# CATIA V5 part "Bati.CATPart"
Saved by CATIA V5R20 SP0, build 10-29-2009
Part number: Bati
Publications: "Hauteur_AxeA"
Bounding box of the stored display mesh (mm): x -50 to 80, y -275.237 to 100, z 0 to 503.17
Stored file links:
  F:\IAO\Projet_IAO5.0\Bati.CATPart
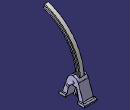
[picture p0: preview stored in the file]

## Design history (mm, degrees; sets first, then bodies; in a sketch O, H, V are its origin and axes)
Parameters
  Hauteur_AxeA = 120 mm
Body1 (main body)
  Sketch1 on yz-plane, origin (0, 0, 0), H (0, 1, 0), V (0, 0, 1)
    point P1 (0, 120)
    point P2 (42.4456, 134.9456)
    point P3 (100, 0)
    arc A1 centre (0, 120) radius 45 from (42.4456, 134.9456) to (0, 165) ccw
    axis line L1 (0, 0) -> (0, 145)
    point P5 (0, 165)
    arc A2 centre (90, 30) radius 10 from (80.5676, 26.6788) to (90, 20) ccw
    point P6 (90, 30)
    arc A3 centre (90, 10) radius 10 from (100, 10) to (90, 20) ccw
    line L2 (100, 0) -> (100, 10)
    point P8 (100, 10)
    line L3 (42.4456, 134.9456) -> (80.5676, 26.6788)
    point P9 (80.5676, 26.6788)
    point P10 (90, 20)
    point P11 (0, 0)
    point P12 (-100, 0)
    point P13 (-100, 10)
    line L4 (-100, 0) -> (-100, 10)
    point P14 (-90, 20)
    arc A4 centre (-90, 10) radius 10 from (-100, 10) to (-90, 20) cw
    point P16 (-80.5676, 26.6788)
    arc A5 centre (-90, 30) radius 10 from (-80.5676, 26.6788) to (-90, 20) cw
    point P18 (-42.4456, 134.9456)
    line L5 (-42.4456, 134.9456) -> (-80.5676, 26.6788)
    point P19 (0, 165)
    arc A6 centre (0, 120) radius 45 from (-42.4456, 134.9456) to (0, 165) cw
    line L6 (100, 0) -> (-100, 0)
    distance P1 O = 120 {= Hauteur_AxeA}
    radius A1 = 45
    distance P3 O = 100
    radius A2 = 10
    radius A3 = 10
    distance P6 L1 = 90
    coincidence: P3 H, L1 P5, P1 V, O P11, P5 P19
    vertical: L1 V, L2 V
    tangency: L2 A3, A2 A3, L3 A2, A1 L3, L6 A3
    symmetry: O P11 L1, P3 P12 L1, P8 P13 L1, L2 L4 L1, P10 P14 L1, A3 A4 L1, P9 P16 L1, A2 A5 L1, P2 P18 L1, L3 L5 L1, P5 P19 L1, A1 A6 L1
  Pad1: profile Sketch1, direction (1, 0, 0), length 40, mirrored extent
  Sketch2 on yz-plane, origin (0, 0, 0), H (0, 1, 0), V (0, 0, 1)
    arc A1 centre (90, 10) radius 10 from (100, 10) to (90, 20) ccw
    point P1 (90, 10)
    line L1 (0, 20) -> (90, 20)
    point P2 (0, 20)
    point P3 (90, 20)
    point P4 (100, 0)
    line L2 (100, 0) -> (100, 10)
    point P5 (100, 10)
    point P6 (100, 10)
    point P7 (-100, 0)
    point P8 (-100, 10)
    line L3 (-100, 0) -> (-100, 10)
    point P9 (-90, 20)
    point P10 (-100, 10)
    arc A2 centre (-90, 10) radius 10 from (-100, 10) to (-90, 20) cw
    point P12 (0, 20)
    line L4 (0, 20) -> (-90, 20)
    line L5 (100, 0) -> (-100, 0)
    radius A1 = 10
    distance V P1 = 90
    distance P2 H = 20
    coincidence: P2 V, L2 P6, L5 H, P5 A1, P2 P12, P5 P6, P8 P10
    tangency: L1 A1, A1 L2, L5 A1
    vertical: L2 V
    symmetry: P4 P7 V, P5 P8 V, L2 L3 V, P3 P9 V, P6 P10 V, A1 A2 V, P2 P12 V, L1 L4 V
  Pad2: profile Sketch2, direction (1, 0, 0), length 50, mirrored extent
  Sketch3 on end face of Pad2, origin (50, 0, 0), H (0, 1, 0), V (0, 0, 1)
    point P1 (-50, 0)
    line L1 (-50, 0) -> (-30, 100)
    line L2 (-30, 100) -> (30, 100)
    point P3 (30, 100)
    line L3 (30, 100) -> (50, 0)
    point P4 (50, 0)
    line L4 (50, 0) -> (-50, 0)
    axis line L5 (0, -25) -> (0, 128)
    point P5 (0, -25)
    distance L5 P3 = 30
    length L2 = 60
    distance H L2 = 100 {= Hauteur_AxeA -20mm}
    length L4 = 100
    distance L5 P4 = 50
    coincidence: P1 H, P4 H, P5 V
    horizontal: L2 H, L4 H
    vertical: L5 V
  Pocket1: profile Sketch3, direction (-1, 0, 0), length 80
  Sketch4 on face of Pocket1 from Sketch3.L2, origin (0, 0, 100), H (1, 0, 0), V (0, -1, 0)
    line L1 (-30, 30) -> (20, 30)
    line L2 (20, 30) -> (20, -30)
    line L3 (20, -30) -> (-30, -30)
    line L4 (-30, -30) -> (-30, 30)
    length L1 = 50
    distance L1 L3 = 60
    distance L1 H = 30
    distance L4 V = 30
    horizontal: L1 H, L3 H
    vertical: L2 V, L4 V
  Pocket2: profile Sketch4, direction (0, 0, -1), up to face of Pad1 from Sketch1.A1
  Sketch5 on end face of Pad1, origin (40, 0, 0), H (0, 1, 0), V (0, 0, 1)
    circle A1 centre (0, 120) radius 10
    point P1 (0, 120)
    radius A1 = 10
    distance H P1 = 120 {= Hauteur_AxeA}
    coincidence: V P1
  Pocket3: profile Sketch5, direction (-1, 0, 0), up to face of Pocket2 from Sketch4.L2
  Sketch6 on face of Pocket2, origin (-30, 0, 0), H (0, 1, 0), V (0, 0, 1)
    arc A1 centre (-380, 120) radius 365 from (-35.29, 0) to (-275.237, 469.6423) ccw
    point P1 (-380, 120)
    arc A2 centre (-380, 120) radius 400 from (1.5757, 0) to (-265.1913, 503.1696) ccw
    point P2 (-380, 120)
    line L1 (-35.29, 0) -> (1.5757, 0)
    point P3 (-35.29, 0)
    line L2 (-275.237, 469.6423) -> (-265.1913, 503.1696)
    radius A1 = 365
    radius A2 = 400
    distance P2 H = 120 {= Hauteur_AxeA}
    distance P2 V = 380
    coincidence: P2 P1, P3 H, L2 P2
    horizontal: L1 H
  Pad3: profile Sketch6, direction (1, 0, 0), length 30
  Sketch7 on end face of Pad3, origin (0, 0, 0), H (0, 1, 0), V (0, 0, 1)
    circle A1 centre (-380, 120) radius 375
    point P1 (-380, 120)
    circle A2 centre (-380, 120) radius 390
    radius A1 = 375
    radius A2 = 390
    distance P1 V = 380
    distance P1 H = 120 {= Hauteur_AxeA}
  Pocket4: profile Sketch7, direction (-1, 0, 0), length 15
  Sketch8 on face of Pocket2 from Sketch4.L2, origin (20, 0, 0), H (0, -1, 0), V (0, 0, 1)
    circle A1 centre (0, 120) radius 10
    point P1 (0, 120)
    radius A1 = 10
    distance H P1 = 120 {= Hauteur_AxeA}
    coincidence: P1 V
  Pad4: profile Sketch8, direction (1, 0, 0), length 60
